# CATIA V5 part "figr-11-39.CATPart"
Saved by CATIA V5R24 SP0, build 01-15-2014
Part number: Part1
Bounding box of the stored display mesh (mm): x -177 to 59, y -180 to 60, z 0 to 80
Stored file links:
  D:\KAVITA\CATIA V5-6R2014 Project_ Kavita\CATIA V5-6R2014_partfiles\Partfiles\c11_catia_v5-6r2014_prt\figr-11-39.CATPart
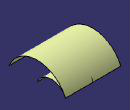
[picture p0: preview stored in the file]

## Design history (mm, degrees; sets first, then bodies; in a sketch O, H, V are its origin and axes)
Set1
  Extrude1: Element1 Sketch1, Lim1 59, Lim2 59, Direction yz-plane
  Scaling1: ToTransfor Extrude1, Reference vertex [face of Extrude1], Ratio 2
Body1 (main body)
  Sketch1 on yz-plane, origin (0, 0, 0), H (0, 1, 0), V (0, 0, 1)
    arc A1 centre (0, -25) radius 65 from (-60, 0) to (60, 0) cw
    point P2 (-60, 0)
    point P3 (60, 0)
    coincidence: P2 H, P3 H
